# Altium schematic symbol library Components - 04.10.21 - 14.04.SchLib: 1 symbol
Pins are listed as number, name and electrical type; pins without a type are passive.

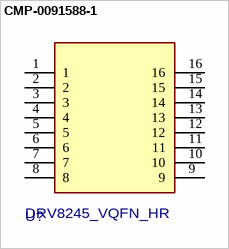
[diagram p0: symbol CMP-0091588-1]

## CMP-0091588-1
designator U?, comment DRV8245_VQFN_HR
Manufacturer: Texas Instruments; Standoff Height: 0mm; SizeZ_mm: 1mm
footprint RXZ0016A-MFG
pins: 1, 2, 3, 4, 5, 6, 7, 8, 9, 10, 11, 12, 13, 14, 15, 16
